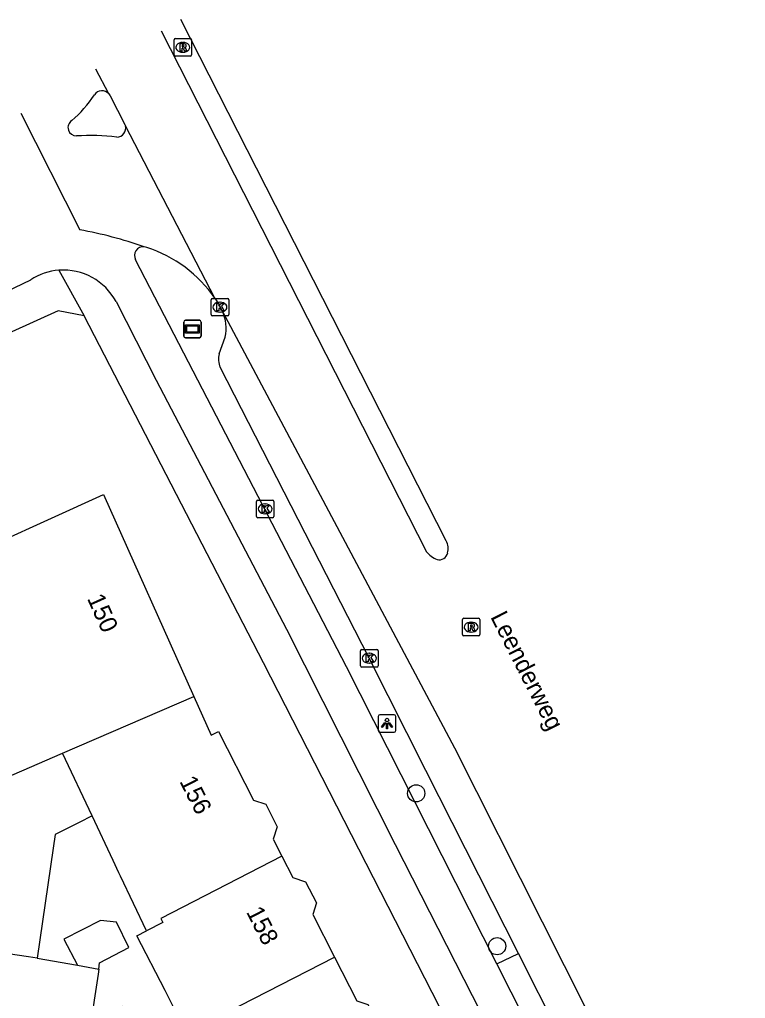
# Model space of a CAD drawing. Extents: x 162250 to 162654, y 380744 to 381605.
# Drawn here: x 162368.1 to 162409.4, y 381549.2 to 381605 of the extents above; entities that cross this region are included whole.
import ezdxf

# ---------------------------------------------------------------- set-up
doc = ezdxf.new("R2010")
doc.units = 0
for name, color, linetype in [('IMGEO_Berm_open', 7, 'Continuous'), ('IMGEO_Boom', 7, 'Continuous'), ('IMGEO_Fietspad_gesloten', 7, 'Continuous'), ('IMGEO_Kolk', 7, 'Continuous'), ('IMGEO_Lichtpunt', 7, 'Continuous'), ('IMGEO_Openbare_ruimte_label', 7, 'Continuous'), ('IMGEO_Pand', 7, 'Continuous'), ('IMGEO_Pand_nummerreeks', 7, 'Continuous'), ('IMGEO_Parkeervlak_open', 7, 'Continuous'), ('IMGEO_Reclamebord', 7, 'Continuous'), ('IMGEO_Rijbaan_lokaal_open', 7, 'Continuous'), ('IMGEO_Rijbaan_regionaal_gesloten', 7, 'Continuous'), ('IMGEO_Rioolput', 7, 'Continuous'), ('IMGEO_Voetpad_open', 7, 'Continuous')]:
    doc.layers.add(name, color=color, linetype=linetype)

msp = doc.modelspace()

# ---------------------------------------------------------------- linework, layer by layer
at = {"layer": 'IMGEO_Berm_open'}
msp.add_lwpolyline([(162395.284, 381551.21), (162396.502, 381551.808)], dxfattribs=at)
at = {"layer": 'IMGEO_Boom'}
for centre in [(162390.684, 381560.919), (162395.29, 381552.218)]:
    msp.add_circle(centre, 0.489, dxfattribs=at)
at = {"layer": 'IMGEO_Fietspad_gesloten'}
for points in [[(162395.284, 381551.21), (162386.719, 381568.128), (162377.717, 381585.46), (162374.695, 381591.279)], [(162362.366, 381587.111), (162368.725, 381590.143)], [(162373.585, 381588.91), (162375.873, 381584.438), (162383.286, 381570.262), (162389.481, 381558.016), (162395.82, 381545.575), (162418.876, 381500), (162423.197, 381491.458), (162446.904, 381444.637), (162457.136, 381424.429), (162474.154, 381390.568), (162476.043, 381386.824)], [(162406.674, 381528.711), (162395.284, 381551.21)]]:
    msp.add_lwpolyline(points, dxfattribs=at)
for centre, radius, start, end in [((162375.145, 381591.517), 0.509, 85.2574, 207.8608), ((162370.595, 381587.287), 3.414, 94.3366, 123.2143), ((162370.589, 381587.299), 3.402, 28.2723, 94.2525)]:
    msp.add_arc(centre, radius, start, end, dxfattribs=at)
at = {"layer": 'IMGEO_Kolk'}
for p, q in [((162379.004, 381588.162), (162379.004, 381589.014)), ((162379.079, 381589.088), (162379.931, 381589.088)), ((162379.492, 381588.868), (162379.517, 381588.868)), ((162380.005, 381589.014), (162380.005, 381588.162)), ((162379.931, 381588.088), (162379.079, 381588.088)), ((162379.515, 381588.308), (162379.49, 381588.308)), ((162381.58, 381576.681), (162381.58, 381577.533)), ((162381.655, 381577.607), (162382.507, 381577.607)), ((162382.581, 381577.533), (162382.581, 381576.681)), ((162382.068, 381577.387), (162382.093, 381577.387)), ((162382.507, 381576.607), (162381.655, 381576.607)), ((162382.091, 381576.827), (162382.066, 381576.827)), ((162387.587, 381569.108), (162388.439, 381569.108)), ((162387.512, 381568.182), (162387.512, 381569.034)), ((162388, 381568.888), (162388.025, 381568.888)), ((162388.513, 381569.034), (162388.513, 381568.182)), ((162388.439, 381568.108), (162387.587, 381568.108)), ((162388.023, 381568.328), (162387.998, 381568.328))]:
    msp.add_line(p, q, dxfattribs=at)
for points in [[(162379.004, 381588.162), (162379.004, 381589.014)], [(162379.079, 381589.088), (162379.931, 381589.088)], [(162379.325, 381588.788), (162379.448, 381588.788), (162379.448, 381588.637), (162379.578, 381588.788), (162379.742, 381588.788), (162379.596, 381588.637), (162379.749, 381588.388), (162379.597, 381588.388), (162379.512, 381588.552), (162379.448, 381588.485), (162379.448, 381588.388), (162379.325, 381588.388), (162379.325, 381588.788)], [(162380.005, 381589.014), (162380.005, 381588.162)], [(162379.931, 381588.088), (162379.079, 381588.088)], [(162381.58, 381576.681), (162381.58, 381577.533)], [(162381.655, 381577.607), (162382.507, 381577.607)], [(162382.581, 381577.533), (162382.581, 381576.681)], [(162381.901, 381577.307), (162382.024, 381577.307), (162382.024, 381577.156), (162382.154, 381577.307), (162382.318, 381577.307), (162382.172, 381577.156), (162382.325, 381576.907), (162382.173, 381576.907), (162382.088, 381577.071), (162382.024, 381577.004), (162382.024, 381576.907), (162381.901, 381576.907), (162381.901, 381577.307)], [(162382.507, 381576.607), (162381.655, 381576.607)], [(162387.587, 381569.108), (162388.439, 381569.108)], [(162387.512, 381568.182), (162387.512, 381569.034)], [(162387.833, 381568.808), (162387.956, 381568.808), (162387.956, 381568.657), (162388.086, 381568.808), (162388.25, 381568.808), (162388.104, 381568.657), (162388.257, 381568.408), (162388.105, 381568.408), (162388.02, 381568.572), (162387.956, 381568.505), (162387.956, 381568.408), (162387.833, 381568.408), (162387.833, 381568.808)], [(162388.513, 381569.034), (162388.513, 381568.182)], [(162388.439, 381568.108), (162387.587, 381568.108)]]:
    msp.add_lwpolyline(points, dxfattribs=at)
for centre, start, end in [((162379.081, 381589.012), 91.552, 178.448), ((162379.081, 381589.012), 91.552, 178.448), ((162379.929, 381589.012), 1.552, 88.448), ((162379.929, 381589.012), 1.552, 88.448), ((162379.081, 381588.164), 181.552, 268.448), ((162379.081, 381588.164), 181.552, 268.448), ((162379.929, 381588.164), 271.552, 358.448), ((162379.929, 381588.164), 271.552, 358.448), ((162381.657, 381577.531), 91.552, 178.448), ((162381.657, 381577.531), 91.552, 178.448), ((162382.505, 381577.531), 1.552, 88.448), ((162382.505, 381577.531), 1.552, 88.448), ((162381.657, 381576.683), 181.552, 268.448), ((162381.657, 381576.683), 181.552, 268.448), ((162382.505, 381576.683), 271.552, 358.448), ((162382.505, 381576.683), 271.552, 358.448), ((162387.589, 381569.032), 91.552, 178.448), ((162387.589, 381569.032), 91.552, 178.448), ((162388.437, 381569.032), 1.552, 88.448), ((162388.437, 381569.032), 1.552, 88.448), ((162387.589, 381568.184), 181.552, 268.448), ((162387.589, 381568.184), 181.552, 268.448), ((162388.437, 381568.184), 271.552, 358.448), ((162388.437, 381568.184), 271.552, 358.448)]:
    msp.add_arc(centre, 0.0765, start, end, dxfattribs=at)
for centre, major_axis, ratio, start_param, end_param in [((162379.491, 381588.588), (-0.387, 0.002), 0.722429, 4.712389, 7.853982), ((162379.516, 381588.588), (-0.39, 0.002), 0.717154, 1.570796, 4.712389), ((162382.067, 381577.107), (-0.387, 0.002), 0.722429, 4.712389, 7.853982), ((162382.092, 381577.107), (-0.39, 0.002), 0.717154, 1.570796, 4.712389), ((162387.999, 381568.608), (-0.387, 0.002), 0.722429, 4.712389, 7.853982), ((162388.024, 381568.608), (-0.39, 0.002), 0.717154, 1.570796, 4.712389)]:
    msp.add_ellipse(centre, major_axis=major_axis, ratio=ratio, start_param=start_param, end_param=end_param, dxfattribs=at)
at = {"layer": 'IMGEO_Lichtpunt'}
for p, q in [((162388.52, 381565.294), (162388.52, 381564.487)), ((162388.52, 381565.294), (162388.52, 381564.487)), ((162389.422, 381565.389), (162388.614, 381565.389)), ((162389.422, 381565.389), (162388.614, 381565.389)), ((162389.516, 381564.487), (162389.516, 381565.294)), ((162389.516, 381564.487), (162389.516, 381565.294)), ((162388.614, 381564.393), (162389.422, 381564.393)), ((162388.614, 381564.393), (162389.422, 381564.393))]:
    msp.add_line(p, q, dxfattribs=at)
for points in [[(162388.894, 381564.958), (162388.933, 381564.93), (162388.745, 381564.668), (162388.707, 381564.695), (162388.894, 381564.958)], [(162388.996, 381564.91), (162389.043, 381564.91), (162389.043, 381564.588), (162388.996, 381564.588), (162388.996, 381564.91)], [(162389.106, 381564.93), (162389.144, 381564.957), (162389.331, 381564.695), (162389.292, 381564.667), (162389.106, 381564.93)]]:
    msp.add_lwpolyline(points, dxfattribs=at)
msp.add_circle((162389.019, 381565.092), 0.0994, dxfattribs=at)
for centre, start, end in [((162388.614, 381565.294), 90, 180), ((162388.614, 381565.294), 90, 180), ((162389.422, 381565.294), 0, 90), ((162389.422, 381565.294), 0, 90), ((162388.614, 381564.487), 180, 270), ((162388.614, 381564.487), 180, 270), ((162389.422, 381564.487), 270, 0), ((162389.422, 381564.487), 270, 360)]:
    msp.add_arc(centre, 0.0946, start, end, dxfattribs=at)
at = {"layer": 'IMGEO_Pand'}
for points in [[(162365.892, 381561.203), (162364.621, 381560.554), (162362.492, 381565.45), (162363.761, 381573.782), (162372.868, 381577.935), (162378.015, 381566.424)], [(162370.539, 381563.206), (162378.015, 381566.424)], [(162378.015, 381566.424), (162379, 381564.222), (162379.419, 381564.436), (162381.416, 381560.526), (162382.114, 381560.3), (162382.768, 381559.02), (162382.54, 381558.316), (162383.037, 381557.342)], [(162365.892, 381561.203), (162370.539, 381563.206)], [(162372.222, 381559.644), (162370.539, 381563.206)], [(162372.222, 381559.644), (162371.482, 381559.266), (162370.126, 381558.573), (162370.012, 381557.797), (162369.092, 381551.537)], [(162375.316, 381553.093), (162373.848, 381556.2), (162373.753, 381556.402), (162373.429, 381557.089), (162372.222, 381559.644)], [(162383.037, 381557.342), (162376.136, 381553.8), (162376.252, 381553.572), (162375.316, 381553.093)], [(162383.037, 381557.342), (162383.66, 381556.123), (162384.384, 381555.889), (162384.999, 381554.685), (162384.786, 381554.027), (162386.023, 381551.605)], [(162372.603, 381550.922), (162372.647, 381551.264), (162374.324, 381552.139), (162373.619, 381553.592), (162372.702, 381553.691), (162370.612, 381552.611), (162371.399, 381551.133)], [(162373.709, 381545.286), (162372.399, 381547.994), (162373.994, 381548.809), (162374.787, 381547.256), (162377.034, 381548.403), (162376.376, 381549.692), (162374.779, 381552.819), (162375.316, 381553.093)], [(162369.092, 381551.537), (162368.602, 381551.623), (162360.753, 381552.779)], [(162369.092, 381551.537), (162371.399, 381551.133)], [(162375.313, 381546.109), (162386.023, 381551.605)], [(162386.023, 381551.605), (162387.294, 381549.116), (162387.927, 381548.911), (162388.553, 381547.687), (162388.331, 381547.003), (162388.92, 381545.85)], [(162372.603, 381550.922), (162372.56, 381550.628), (162372.342, 381549.148), (162372.151, 381547.849), (162368.544, 381548.38), (162368.21, 381546.113)], [(162371.399, 381551.133), (162372.603, 381550.922)]]:
    msp.add_lwpolyline(points, dxfattribs=at)
at = {"layer": 'IMGEO_Parkeervlak_open'}
for points in [[(162379.454, 381585.937), (162379.797, 381586.88)], [(162396.502, 381551.808), (162391.23, 381562.225), (162388.01, 381568.609), (162379.519, 381585.166)], [(162407.881, 381529.368), (162404.362, 381536.357), (162402.33, 381540.282), (162398.81, 381547.248), (162396.502, 381551.808)]]:
    msp.add_lwpolyline(points, dxfattribs=at)
for centre, radius, start, end in [((162377.563, 381587.398), 2.293, 346.9554, 25.3135), ((162380.625, 381585.647), 1.206, 166.1078, 203.5302)]:
    msp.add_arc(centre, radius, start, end, dxfattribs=at)
at = {"layer": 'IMGEO_Reclamebord'}
for p, q in [((162377.441, 381586.944), (162377.441, 381587.744)), ((162377.441, 381587.744), (162377.441, 381586.944)), ((162377.541, 381587.844), (162378.331, 381587.844)), ((162378.331, 381587.844), (162377.541, 381587.844)), ((162378.431, 381587.744), (162378.431, 381586.944)), ((162378.431, 381586.944), (162378.431, 381587.744)), ((162378.331, 381586.844), (162377.541, 381586.844)), ((162377.541, 381586.844), (162378.331, 381586.844))]:
    msp.add_line(p, q, dxfattribs=at)
for points in [[(162377.542, 381587.576), (162378.33, 381587.576), (162378.33, 381587.112), (162377.542, 381587.112), (162377.542, 381587.576)], [(162377.607, 381587.511), (162377.607, 381587.177), (162378.265, 381587.177), (162378.265, 381587.511), (162377.607, 381587.511)]]:
    msp.add_lwpolyline(points, dxfattribs=at)
for centre, start, end in [((162377.541, 381587.744), 90, 180), ((162377.541, 381587.744), 90, 180), ((162378.331, 381587.744), 0, 90), ((162378.331, 381587.744), 360, 90), ((162377.541, 381586.944), 180, 270), ((162377.541, 381586.944), 180, 270), ((162378.331, 381586.944), 270, 0), ((162378.331, 381586.944), 270, 0)]:
    msp.add_arc(centre, 0.1, start, end, dxfattribs=at)
at = {"layer": 'IMGEO_Rijbaan_lokaal_open'}
msp.add_lwpolyline([(162368.165, 381599.637), (162371.523, 381592.991)], dxfattribs=at)
for centre, radius, start, end in [((162372.788, 381600.399), 0.51, 40.1005, 148.3671), ((162366.37, 381604.668), 7.199, 310.6865, 326.2273), ((162371.328, 381598.812), 0.478, 123.6828, 270.6146), ((162373.619, 381598.782), 0.518, 272.2566, 13.1137), ((162372.112, 381585.815), 12.543, 83.0095, 93.5627), ((162367.205, 381569.204), 24.176, 70.7207, 79.7106), ((162375.148, 381591.532), 0.493, 67.5078, 85.5008), ((162373.029, 381584.848), 7.504, 34.4412, 72.0841)]:
    msp.add_arc(centre, radius, start, end, dxfattribs=at)
at = {"layer": 'IMGEO_Rijbaan_regionaal_gesloten'}
for points in [[(162392.392, 381575.292), (162377.276, 381604.956)], [(162376.164, 381604.307), (162391.268, 381574.672)], [(162373.178, 381600.727), (162372.439, 381602.132)], [(162373.178, 381600.727), (162373.249, 381600.615), (162374.095, 381598.985), (162374.123, 381598.9)], [(162379.217, 381589.092), (162374.123, 381598.9)], [(162379.217, 381589.092), (162379.423, 381588.776), (162379.636, 381588.378)], [(162379.636, 381588.378), (162392.859, 381563.507), (162402.855, 381543.709), (162412.668, 381524.385), (162425.065, 381500), (162437.86, 381474.688), (162449.303, 381452.467), (162451.987, 381447.126), (162459.635, 381431.909), (162469.338, 381412.429), (162476.05, 381399.207), (162475.732, 381399.044)]]:
    msp.add_lwpolyline(points, dxfattribs=at)
for centre, radius, start, end in [((162391.529, 381574.84), 0.974, 345.9202, 27.6538), ((162392.36, 381575.532), 1.389, 218.2255, 249.4152), ((162392, 381574.697), 0.484, 254.5729, 348.7692)]:
    msp.add_arc(centre, radius, start, end, dxfattribs=at)
at = {"layer": 'IMGEO_Rioolput'}
for p, q in [((162376.889, 381602.949), (162376.889, 381603.801)), ((162376.964, 381603.875), (162377.816, 381603.875)), ((162377.377, 381603.655), (162377.402, 381603.655)), ((162377.89, 381603.801), (162377.89, 381602.949)), ((162377.4, 381603.095), (162377.375, 381603.095)), ((162377.816, 381602.875), (162376.964, 381602.875)), ((162393.311, 381569.954), (162393.311, 381570.806)), ((162393.386, 381570.88), (162394.238, 381570.88)), ((162394.312, 381570.806), (162394.312, 381569.954)), ((162393.799, 381570.66), (162393.824, 381570.66)), ((162394.238, 381569.88), (162393.386, 381569.88)), ((162393.822, 381570.1), (162393.797, 381570.1))]:
    msp.add_line(p, q, dxfattribs=at)
for points in [[(162376.889, 381602.949), (162376.889, 381603.801)], [(162376.964, 381603.875), (162377.816, 381603.875)], [(162377.89, 381603.801), (162377.89, 381602.949)], [(162377.478, 381603.573), (162377.226, 381603.575), (162377.226, 381603.175)], [(162377.226, 381603.175), (162377.35, 381603.175), (162377.35, 381603.337), (162377.361, 381603.337)], [(162377.404, 381603.494), (162377.35, 381603.494), (162377.35, 381603.413)], [(162377.35, 381603.413), (162377.402, 381603.413)], [(162377.408, 381603.308), (162377.479, 381603.175), (162377.619, 381603.175), (162377.554, 381603.301)], [(162377.816, 381602.875), (162376.964, 381602.875)], [(162393.311, 381569.954), (162393.311, 381570.806)], [(162393.386, 381570.88), (162394.238, 381570.88)], [(162394.312, 381570.806), (162394.312, 381569.954)], [(162393.9, 381570.578), (162393.648, 381570.58), (162393.648, 381570.18)], [(162393.648, 381570.18), (162393.772, 381570.18), (162393.772, 381570.342), (162393.783, 381570.342)], [(162393.826, 381570.499), (162393.772, 381570.499), (162393.772, 381570.418)], [(162393.772, 381570.418), (162393.824, 381570.418)], [(162393.83, 381570.313), (162393.901, 381570.18), (162394.041, 381570.18), (162393.976, 381570.306)], [(162394.238, 381569.88), (162393.386, 381569.88)]]:
    msp.add_lwpolyline(points, dxfattribs=at)
for centre, radius, start, end in [((162376.966, 381603.799), 0.0765, 91.552, 178.448), ((162376.966, 381603.799), 0.0765, 91.552, 178.448), ((162377.814, 381603.799), 0.0765, 1.552, 88.448), ((162377.814, 381603.799), 0.0765, 1.552, 88.448), ((162377.36, 381603.284), 0.0533, 26.0293, 88.6989), ((162377.386, 381603.602), 0.19, 274.7715, 282.9687), ((162377.41, 381603.398), 0.0964, 77.0061, 93.1865), ((162377.424, 381603.455), 0.0378, 276.6634, 79.6772), ((162377.477, 381603.463), 0.109, 350.3612, 89.416), ((162377.475, 381603.463), 0.112, 277.5842, 350.9817), ((162377.459, 381603.248), 0.108, 29.5134, 73.7905), ((162376.966, 381602.951), 0.0765, 181.552, 268.448), ((162376.966, 381602.951), 0.0765, 181.552, 268.448), ((162377.814, 381602.951), 0.0765, 271.552, 358.448), ((162377.814, 381602.951), 0.0765, 271.552, 358.448), ((162393.388, 381570.804), 0.0765, 91.552, 178.448), ((162393.388, 381570.804), 0.0765, 91.552, 178.448), ((162394.236, 381570.804), 0.0765, 1.552, 88.448), ((162394.236, 381570.804), 0.0765, 1.552, 88.448), ((162393.782, 381570.289), 0.0533, 26.0293, 88.6989), ((162393.808, 381570.607), 0.19, 274.7715, 282.9687), ((162393.832, 381570.403), 0.0964, 77.0061, 93.1865), ((162393.846, 381570.46), 0.0378, 276.6634, 79.6772), ((162393.899, 381570.468), 0.109, 350.3612, 89.416), ((162393.897, 381570.468), 0.112, 277.5842, 350.9817), ((162393.881, 381570.253), 0.108, 29.5134, 73.7905), ((162393.388, 381569.956), 0.0765, 181.552, 268.448), ((162393.388, 381569.956), 0.0765, 181.552, 268.448), ((162394.236, 381569.956), 0.0765, 271.552, 358.448), ((162394.236, 381569.956), 0.0765, 271.552, 358.448)]:
    msp.add_arc(centre, radius, start, end, dxfattribs=at)
for centre, major_axis, ratio, start_param, end_param in [((162377.376, 381603.375), (-0.387, 0.002), 0.722429, 4.712389, 7.853982), ((162377.401, 381603.375), (-0.39, 0.002), 0.717154, 1.570796, 4.712389), ((162393.798, 381570.38), (-0.387, 0.002), 0.722429, 4.712389, 7.853982), ((162393.823, 381570.38), (-0.39, 0.002), 0.717154, 1.570796, 4.712389)]:
    msp.add_ellipse(centre, major_axis=major_axis, ratio=ratio, start_param=start_param, end_param=end_param, dxfattribs=at)
at = {"layer": 'IMGEO_Voetpad_open'}
for points in [[(162370.337, 381590.691), (162371.772, 381588.094)], [(162371.772, 381588.094), (162370.283, 381588.375), (162363.369, 381585.251), (162361.6, 381584.081), (162363.286, 381580.314), (162362.669, 381579.584), (162359.448, 381578.123), (162359.403, 381573.306), (162358.055, 381562.41), (162350.929, 381514.861)], [(162474.869, 381385.175), (162465.732, 381403.337), (162448.748, 381437.096), (162445.289, 381443.846), (162433.372, 381467.098), (162422.628, 381488.367), (162420.377, 381492.822), (162416.751, 381500), (162400.772, 381531.631), (162381.991, 381568.34), (162371.772, 381588.094)]]:
    msp.add_lwpolyline(points, dxfattribs=at)

# ---------------------------------------------------------------- texts
at = {"layer": 'IMGEO_Openbare_ruimte_label'}
msp.add_text('Leenderweg', height=1, rotation=297.0007, dxfattribs=at).set_placement((162394.89, 381570.963))
at = {"layer": 'IMGEO_Pand_nummerreeks'}
for s, rotation, p in [('150', 294.0912, (162371.923, 381572.012)), ('156', 297.0319, (162377.179, 381561.608)), ('158', 297.2153, (162380.979, 381554.172))]:
    msp.add_text(s, height=1, rotation=rotation, dxfattribs=at).set_placement(p)

doc.saveas('drawing.dxf')
